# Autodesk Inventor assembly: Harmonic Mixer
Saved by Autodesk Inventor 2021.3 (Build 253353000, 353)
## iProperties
Created: 2022-04
Part Number: Harmonic Mixer
Document SubType Name: Assembly
Designer: Administrator
Title: Harmonic Mixer v3
Author: Administrator
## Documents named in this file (2)
- c:\worker\convert-fusion-r02\tmp\job-1\1356\output\files\befc9bb2-2a2e-4feb-b198-ab99da84b8a8\e38f241a-008d-41b4-8f1f-9dfc49e5feaa.iam
- c:\worker\convert-fusion-r02\tmp\job-1\1356\output\files\befc9bb2-2a2e-4feb-b198-ab99da84b8a8\Component1.ipt
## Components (1 placed, 1 different names)
1. Component1:1
